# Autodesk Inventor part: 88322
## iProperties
Created: 2007-10
Part Number: 88322
Material: 3.2315.71 AlMgSi1 F28
Description: Zentrierring (A2/FPM) DN 20 KF
Document SubType Name: Modellieren
Designer: TMT
Manufacturer: Standard
Standards Organization: Custom
Density: 1 g/cm^3
Vendor: LEYBOLD
Author: TMT
Comments: LEYBOLD
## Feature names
1. Extrusion2
2. Bohrung1 [Hole]
3. Umdrehung1 [Revolution]
4. Umdrehung2 [Revolution]
5. Fase1 [Chamfer]
